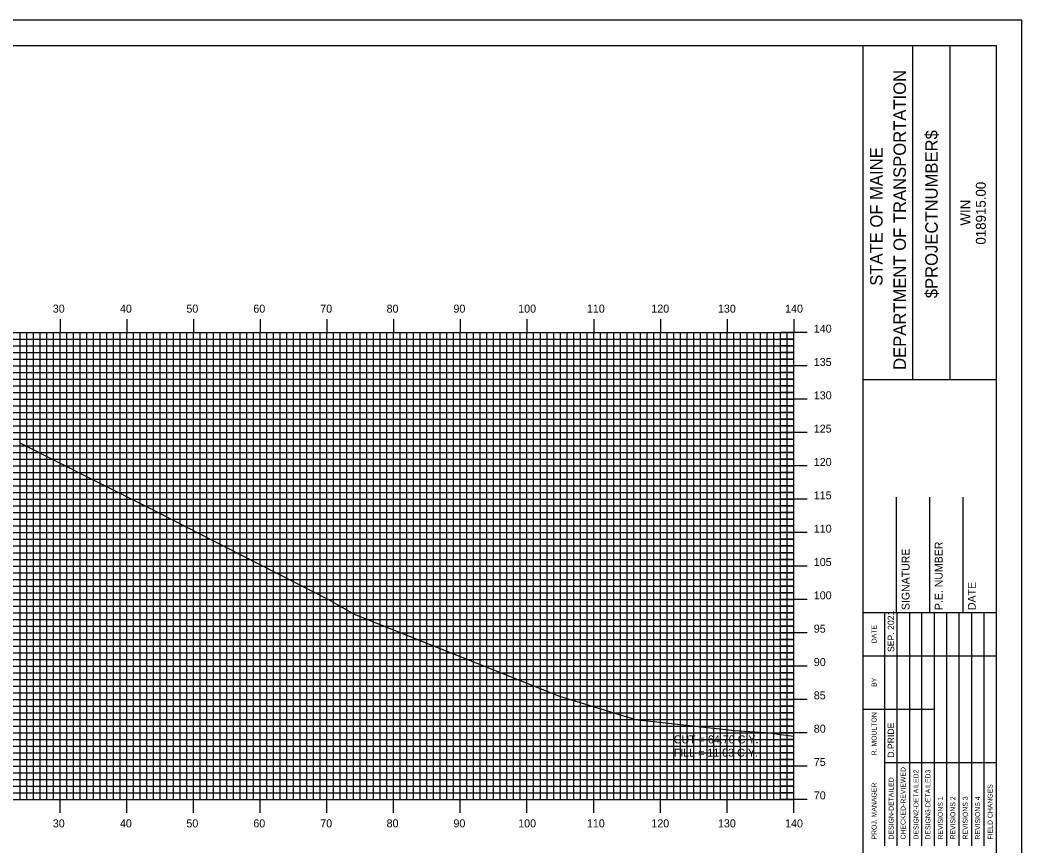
# Model space of a CAD drawing. Extents: x 859078 to 859421, y 364765 to 364985.
# Drawn here: x 859267.3 to 859417.6, y 364861.3 to 364985.2 of the extents above; entities that cross this region are included whole.
import ezdxf

# ---------------------------------------------------------------- set-up
doc = ezdxf.new("R2010")
doc.units = 0
for name, color, linetype in [('BORDER', 7, 'Continuous'), ('D_Text_Standard', 7, 'Continuous'), ('H_V ANNOTATION', 7, 'Continuous'), ('MAJOR', 7, 'Continuous'), ('MINOR', 7, 'Continuous'), ('PLOT BOUNDARY', 7, 'Continuous'), ('S_Roadway_Centerline', 7, 'Continuous')]:
    doc.layers.add(name, color=color, linetype=linetype)

msp = doc.modelspace()

# ---------------------------------------------------------------- linework, layer by layer
at = {"layer": 'BORDER'}
for p, q in [((859393.76, 364771.3), (859393.76, 364981.3)), ((859401.22, 364931.3), (859401.22, 364981.3)), ((859406.81, 364931.3), (859406.81, 364981.3)), ((859393.76, 364931.29), (859413.76, 364931.29)), ((859398.76, 364896.31), (859398.76, 364913.6)), ((859403.76, 364896.31), (859403.76, 364913.6)), ((859408.76, 364896.31), (859408.76, 364913.6)), ((859393.76, 364896.31), (859413.76, 364896.31))]:
    msp.add_line(p, q, dxfattribs=at)
msp.add_lwpolyline([(859093.76, 364771.3), (859413.76, 364771.3), (859413.76, 364981.3), (859093.76, 364981.3)], close=True, dxfattribs=at)
for points in [[(859396.99, 364889.81), (859396.99, 364896.31)], [(859398.85, 364861.31), (859398.85, 364896.31)], [(859400.72, 364896.31), (859400.72, 364861.31)], [(859402.58, 364861.31), (859402.58, 364896.31)], [(859404.45, 364861.31), (859404.45, 364896.31)], [(859406.31, 364861.31), (859406.31, 364896.31)], [(859408.17, 364861.31), (859408.17, 364896.31)], [(859410.04, 364861.31), (859410.04, 364896.31)], [(859411.9, 364861.31), (859411.9, 364896.31)], [(859396.99, 364861.31), (859396.99, 364894.9)], [(859393.76, 364889.81), (859413.76, 364889.81)], [(859393.76, 364881.81), (859396.99, 364881.81)], [(859396.99, 364881.81), (859404.44, 364881.81)], [(859396.99, 364873.81), (859413.76, 364873.81)]]:
    msp.add_lwpolyline(points, dxfattribs=at)
at = {"layer": 'MAJOR'}
for p, q in [((859273.36, 364940.31), (859273.36, 364938.3)), ((859283.36, 364940.31), (859283.36, 364938.3)), ((859293.36, 364940.31), (859293.36, 364938.3)), ((859303.36, 364940.31), (859303.36, 364938.3)), ((859313.36, 364940.31), (859313.36, 364938.3)), ((859323.36, 364940.31), (859323.36, 364938.3)), ((859333.36, 364940.31), (859333.36, 364938.3)), ((859343.36, 364940.31), (859343.36, 364938.3)), ((859353.36, 364940.31), (859353.36, 364938.3)), ((859363.36, 364940.31), (859363.36, 364938.3)), ((859373.36, 364940.31), (859373.36, 364938.3)), ((859383.36, 364940.31), (859383.36, 364938.3)), ((859103.36, 364938.3), (859383.36, 364938.3)), ((859103.36, 364938.3), (859383.36, 364938.3)), ((859273.36, 364868.3), (859273.36, 364938.3)), ((859283.36, 364868.3), (859283.36, 364938.3)), ((859293.36, 364868.3), (859293.36, 364938.3)), ((859303.36, 364868.3), (859303.36, 364938.3)), ((859313.36, 364868.3), (859313.36, 364938.3)), ((859323.36, 364868.3), (859323.36, 364938.3)), ((859333.36, 364868.3), (859333.36, 364938.3)), ((859343.36, 364868.3), (859343.36, 364938.3)), ((859353.36, 364868.3), (859353.36, 364938.3)), ((859363.36, 364868.3), (859363.36, 364938.3)), ((859373.36, 364868.3), (859373.36, 364938.3)), ((859385.36, 364938.3), (859381.36, 364938.3)), ((859383.36, 364868.3), (859383.36, 364938.3)), ((859383.36, 364868.3), (859383.36, 364938.3)), ((859103.36, 364933.3), (859383.36, 364933.3)), ((859385.36, 364933.3), (859381.36, 364933.3)), ((859103.36, 364928.3), (859383.36, 364928.3)), ((859385.36, 364928.3), (859381.36, 364928.3)), ((859103.36, 364923.3), (859383.36, 364923.3)), ((859385.36, 364923.3), (859381.36, 364923.3)), ((859103.36, 364918.3), (859383.36, 364918.3)), ((859385.36, 364918.3), (859381.36, 364918.3)), ((859103.36, 364913.3), (859383.36, 364913.3)), ((859385.36, 364913.3), (859381.36, 364913.3)), ((859103.36, 364908.3), (859383.36, 364908.3)), ((859385.36, 364908.3), (859381.36, 364908.3)), ((859103.36, 364903.3), (859383.36, 364903.3)), ((859385.36, 364903.3), (859381.36, 364903.3)), ((859103.36, 364898.3), (859383.36, 364898.3)), ((859385.36, 364898.3), (859381.36, 364898.3)), ((859103.36, 364893.3), (859383.36, 364893.3)), ((859385.36, 364893.3), (859381.36, 364893.3)), ((859103.36, 364888.3), (859383.36, 364888.3)), ((859385.36, 364888.3), (859381.36, 364888.3)), ((859103.36, 364883.3), (859383.36, 364883.3)), ((859385.36, 364883.3), (859381.36, 364883.3)), ((859103.36, 364878.3), (859383.36, 364878.3)), ((859385.36, 364878.3), (859381.36, 364878.3)), ((859103.36, 364873.3), (859383.36, 364873.3)), ((859385.36, 364873.3), (859381.36, 364873.3)), ((859103.36, 364868.3), (859383.36, 364868.3)), ((859103.36, 364868.3), (859383.36, 364868.3)), ((859273.36, 364866.3), (859273.36, 364868.3)), ((859283.36, 364866.3), (859283.36, 364868.3)), ((859293.36, 364866.3), (859293.36, 364868.3)), ((859303.36, 364866.3), (859303.36, 364868.3)), ((859313.36, 364866.3), (859313.36, 364868.3)), ((859323.36, 364866.3), (859323.36, 364868.3)), ((859333.36, 364866.3), (859333.36, 364868.3)), ((859343.36, 364866.3), (859343.36, 364868.3)), ((859353.36, 364866.3), (859353.36, 364868.3)), ((859363.36, 364866.3), (859363.36, 364868.3)), ((859373.36, 364866.3), (859373.36, 364868.3)), ((859385.36, 364868.3), (859381.36, 364868.3)), ((859383.36, 364866.3), (859383.36, 364868.3))]:
    msp.add_line(p, q, dxfattribs=at)
at = {"layer": 'MINOR'}
for p, q in [((859267.36, 364868.3), (859267.36, 364938.3)), ((859268.36, 364868.3), (859268.36, 364938.3)), ((859269.36, 364868.3), (859269.36, 364938.3)), ((859270.36, 364868.3), (859270.36, 364938.3)), ((859271.36, 364868.3), (859271.36, 364938.3)), ((859272.36, 364868.3), (859272.36, 364938.3)), ((859274.36, 364868.3), (859274.36, 364938.3)), ((859275.36, 364868.3), (859275.36, 364938.3)), ((859276.36, 364868.3), (859276.36, 364938.3)), ((859277.36, 364868.3), (859277.36, 364938.3)), ((859278.36, 364868.3), (859278.36, 364938.3)), ((859279.36, 364868.3), (859279.36, 364938.3)), ((859280.36, 364868.3), (859280.36, 364938.3)), ((859281.36, 364868.3), (859281.36, 364938.3)), ((859282.36, 364868.3), (859282.36, 364938.3)), ((859284.36, 364868.3), (859284.36, 364938.3)), ((859285.36, 364868.3), (859285.36, 364938.3)), ((859286.36, 364868.3), (859286.36, 364938.3)), ((859287.36, 364868.3), (859287.36, 364938.3)), ((859288.36, 364868.3), (859288.36, 364938.3)), ((859289.36, 364868.3), (859289.36, 364938.3)), ((859290.36, 364868.3), (859290.36, 364938.3)), ((859291.36, 364868.3), (859291.36, 364938.3)), ((859292.36, 364868.3), (859292.36, 364938.3)), ((859294.36, 364868.3), (859294.36, 364938.3)), ((859295.36, 364868.3), (859295.36, 364938.3)), ((859296.36, 364868.3), (859296.36, 364938.3)), ((859297.36, 364868.3), (859297.36, 364938.3)), ((859298.36, 364868.3), (859298.36, 364938.3)), ((859299.36, 364868.3), (859299.36, 364938.3)), ((859300.36, 364868.3), (859300.36, 364938.3)), ((859301.36, 364868.3), (859301.36, 364938.3)), ((859302.36, 364868.3), (859302.36, 364938.3)), ((859304.36, 364868.3), (859304.36, 364938.3)), ((859305.36, 364868.3), (859305.36, 364938.3)), ((859306.36, 364868.3), (859306.36, 364938.3)), ((859307.36, 364868.3), (859307.36, 364938.3)), ((859308.36, 364868.3), (859308.36, 364938.3)), ((859309.36, 364868.3), (859309.36, 364938.3)), ((859310.36, 364868.3), (859310.36, 364938.3)), ((859311.36, 364868.3), (859311.36, 364938.3)), ((859312.36, 364868.3), (859312.36, 364938.3)), ((859314.36, 364868.3), (859314.36, 364938.3)), ((859315.36, 364868.3), (859315.36, 364938.3)), ((859316.36, 364868.3), (859316.36, 364938.3)), ((859317.36, 364868.3), (859317.36, 364938.3)), ((859318.36, 364868.3), (859318.36, 364938.3)), ((859319.36, 364868.3), (859319.36, 364938.3)), ((859320.36, 364868.3), (859320.36, 364938.3)), ((859321.36, 364868.3), (859321.36, 364938.3)), ((859322.36, 364868.3), (859322.36, 364938.3)), ((859324.36, 364868.3), (859324.36, 364938.3)), ((859325.36, 364868.3), (859325.36, 364938.3)), ((859326.36, 364868.3), (859326.36, 364938.3)), ((859327.36, 364868.3), (859327.36, 364938.3)), ((859328.36, 364868.3), (859328.36, 364938.3)), ((859329.36, 364868.3), (859329.36, 364938.3)), ((859330.36, 364868.3), (859330.36, 364938.3)), ((859331.36, 364868.3), (859331.36, 364938.3)), ((859332.36, 364868.3), (859332.36, 364938.3)), ((859334.36, 364868.3), (859334.36, 364938.3)), ((859335.36, 364868.3), (859335.36, 364938.3)), ((859336.36, 364868.3), (859336.36, 364938.3)), ((859337.36, 364868.3), (859337.36, 364938.3)), ((859338.36, 364868.3), (859338.36, 364938.3)), ((859339.36, 364868.3), (859339.36, 364938.3)), ((859340.36, 364868.3), (859340.36, 364938.3)), ((859341.36, 364868.3), (859341.36, 364938.3)), ((859342.36, 364868.3), (859342.36, 364938.3)), ((859344.36, 364868.3), (859344.36, 364938.3)), ((859345.36, 364868.3), (859345.36, 364938.3)), ((859346.36, 364868.3), (859346.36, 364938.3)), ((859347.36, 364868.3), (859347.36, 364938.3)), ((859348.36, 364868.3), (859348.36, 364938.3)), ((859349.36, 364868.3), (859349.36, 364938.3)), ((859350.36, 364868.3), (859350.36, 364938.3)), ((859351.36, 364868.3), (859351.36, 364938.3)), ((859352.36, 364868.3), (859352.36, 364938.3)), ((859354.36, 364868.3), (859354.36, 364938.3)), ((859355.36, 364868.3), (859355.36, 364938.3)), ((859356.36, 364868.3), (859356.36, 364938.3)), ((859357.36, 364868.3), (859357.36, 364938.3)), ((859358.36, 364868.3), (859358.36, 364938.3)), ((859359.36, 364868.3), (859359.36, 364938.3)), ((859360.36, 364868.3), (859360.36, 364938.3)), ((859361.36, 364868.3), (859361.36, 364938.3)), ((859362.36, 364868.3), (859362.36, 364938.3)), ((859364.36, 364868.3), (859364.36, 364938.3)), ((859365.36, 364868.3), (859365.36, 364938.3)), ((859366.36, 364868.3), (859366.36, 364938.3)), ((859367.36, 364868.3), (859367.36, 364938.3)), ((859368.36, 364868.3), (859368.36, 364938.3)), ((859369.36, 364868.3), (859369.36, 364938.3)), ((859370.36, 364868.3), (859370.36, 364938.3)), ((859371.36, 364868.3), (859371.36, 364938.3)), ((859372.36, 364868.3), (859372.36, 364938.3)), ((859374.36, 364868.3), (859374.36, 364938.3)), ((859375.36, 364868.3), (859375.36, 364938.3)), ((859376.36, 364868.3), (859376.36, 364938.3)), ((859377.36, 364868.3), (859377.36, 364938.3)), ((859378.36, 364868.3), (859378.36, 364938.3)), ((859379.36, 364868.3), (859379.36, 364938.3)), ((859380.36, 364868.3), (859380.36, 364938.3)), ((859381.36, 364868.3), (859381.36, 364938.3)), ((859382.36, 364868.3), (859382.36, 364938.3)), ((859103.36, 364937.3), (859383.36, 364937.3)), ((859383.36, 364937.3), (859381.36, 364937.3)), ((859103.36, 364936.3), (859383.36, 364936.3)), ((859103.36, 364935.3), (859383.36, 364935.3)), ((859383.36, 364936.3), (859381.36, 364936.3)), ((859383.36, 364935.3), (859381.36, 364935.3)), ((859103.36, 364934.3), (859383.36, 364934.3)), ((859383.36, 364934.3), (859381.36, 364934.3)), ((859103.36, 364932.3), (859383.36, 364932.3)), ((859383.36, 364932.3), (859381.36, 364932.3)), ((859103.36, 364931.3), (859383.36, 364931.3)), ((859383.36, 364931.3), (859381.36, 364931.3)), ((859103.36, 364930.3), (859383.36, 364930.3)), ((859103.36, 364929.3), (859383.36, 364929.3)), ((859383.36, 364930.3), (859381.36, 364930.3)), ((859383.36, 364929.3), (859381.36, 364929.3)), ((859103.36, 364927.3), (859383.36, 364927.3)), ((859103.36, 364926.3), (859383.36, 364926.3)), ((859383.36, 364927.3), (859381.36, 364927.3)), ((859383.36, 364926.3), (859381.36, 364926.3)), ((859103.36, 364925.3), (859383.36, 364925.3)), ((859383.36, 364925.3), (859381.36, 364925.3)), ((859103.36, 364924.3), (859383.36, 364924.3)), ((859383.36, 364924.3), (859381.36, 364924.3)), ((859103.36, 364922.3), (859383.36, 364922.3)), ((859383.36, 364922.3), (859381.36, 364922.3)), ((859103.36, 364921.3), (859383.36, 364921.3)), ((859103.36, 364920.3), (859383.36, 364920.3)), ((859383.36, 364921.3), (859381.36, 364921.3)), ((859383.36, 364920.3), (859381.36, 364920.3)), ((859103.36, 364919.3), (859383.36, 364919.3)), ((859383.36, 364919.3), (859381.36, 364919.3)), ((859103.36, 364917.3), (859383.36, 364917.3)), ((859383.36, 364917.3), (859381.36, 364917.3)), ((859103.36, 364916.3), (859383.36, 364916.3)), ((859383.36, 364916.3), (859381.36, 364916.3)), ((859103.36, 364915.3), (859383.36, 364915.3)), ((859103.36, 364914.3), (859383.36, 364914.3)), ((859383.36, 364915.3), (859381.36, 364915.3)), ((859383.36, 364914.3), (859381.36, 364914.3)), ((859103.36, 364912.3), (859383.36, 364912.3)), ((859103.36, 364911.3), (859383.36, 364911.3)), ((859383.36, 364912.3), (859381.36, 364912.3)), ((859383.36, 364911.3), (859381.36, 364911.3)), ((859103.36, 364910.3), (859383.36, 364910.3)), ((859383.36, 364910.3), (859381.36, 364910.3)), ((859103.36, 364909.3), (859383.36, 364909.3)), ((859383.36, 364909.3), (859381.36, 364909.3)), ((859103.36, 364907.3), (859383.36, 364907.3)), ((859383.36, 364907.3), (859381.36, 364907.3)), ((859103.36, 364906.3), (859383.36, 364906.3)), ((859103.36, 364905.3), (859383.36, 364905.3)), ((859383.36, 364906.3), (859381.36, 364906.3)), ((859383.36, 364905.3), (859381.36, 364905.3)), ((859103.36, 364904.3), (859383.36, 364904.3)), ((859383.36, 364904.3), (859381.36, 364904.3)), ((859103.36, 364902.3), (859383.36, 364902.3)), ((859383.36, 364902.3), (859381.36, 364902.3)), ((859103.36, 364901.3), (859383.36, 364901.3)), ((859383.36, 364901.3), (859381.36, 364901.3)), ((859103.36, 364900.3), (859383.36, 364900.3)), ((859103.36, 364899.3), (859383.36, 364899.3)), ((859383.36, 364900.3), (859381.36, 364900.3)), ((859383.36, 364899.3), (859381.36, 364899.3)), ((859103.36, 364897.3), (859383.36, 364897.3)), ((859103.36, 364896.3), (859383.36, 364896.3)), ((859383.36, 364897.3), (859381.36, 364897.3)), ((859383.36, 364896.3), (859381.36, 364896.3)), ((859103.36, 364895.3), (859383.36, 364895.3)), ((859383.36, 364895.3), (859381.36, 364895.3)), ((859103.36, 364894.3), (859383.36, 364894.3)), ((859383.36, 364894.3), (859381.36, 364894.3)), ((859103.36, 364892.3), (859383.36, 364892.3)), ((859383.36, 364892.3), (859381.36, 364892.3)), ((859103.36, 364891.3), (859383.36, 364891.3)), ((859103.36, 364890.3), (859383.36, 364890.3)), ((859383.36, 364891.3), (859381.36, 364891.3)), ((859383.36, 364890.3), (859381.36, 364890.3)), ((859103.36, 364889.3), (859383.36, 364889.3)), ((859383.36, 364889.3), (859381.36, 364889.3)), ((859103.36, 364887.3), (859383.36, 364887.3)), ((859383.36, 364887.3), (859381.36, 364887.3)), ((859103.36, 364886.3), (859383.36, 364886.3)), ((859383.36, 364886.3), (859381.36, 364886.3)), ((859103.36, 364885.3), (859383.36, 364885.3)), ((859103.36, 364884.3), (859383.36, 364884.3)), ((859383.36, 364885.3), (859381.36, 364885.3)), ((859383.36, 364884.3), (859381.36, 364884.3)), ((859103.36, 364882.3), (859383.36, 364882.3)), ((859103.36, 364881.3), (859383.36, 364881.3)), ((859383.36, 364882.3), (859381.36, 364882.3)), ((859383.36, 364881.3), (859381.36, 364881.3)), ((859103.36, 364880.3), (859383.36, 364880.3)), ((859383.36, 364880.3), (859381.36, 364880.3)), ((859103.36, 364879.3), (859383.36, 364879.3)), ((859383.36, 364879.3), (859381.36, 364879.3)), ((859103.36, 364877.3), (859383.36, 364877.3)), ((859383.36, 364877.3), (859381.36, 364877.3)), ((859103.36, 364876.3), (859383.36, 364876.3)), ((859103.36, 364875.3), (859383.36, 364875.3)), ((859383.36, 364876.3), (859381.36, 364876.3)), ((859383.36, 364875.3), (859381.36, 364875.3)), ((859103.36, 364874.3), (859383.36, 364874.3)), ((859383.36, 364874.3), (859381.36, 364874.3)), ((859103.36, 364872.3), (859383.36, 364872.3)), ((859383.36, 364872.3), (859381.36, 364872.3)), ((859103.36, 364871.3), (859383.36, 364871.3)), ((859103.36, 364870.3), (859383.36, 364870.3)), ((859383.36, 364871.3), (859381.36, 364871.3)), ((859383.36, 364870.3), (859381.36, 364870.3)), ((859103.36, 364869.3), (859383.36, 364869.3)), ((859383.36, 364869.3), (859381.36, 364869.3))]:
    msp.add_line(p, q, dxfattribs=at)
at = {"layer": 'PLOT BOUNDARY'}
msp.add_lwpolyline([(859077.57, 364765.18), (859417.57, 364765.18), (859417.57, 364985.18), (859077.57, 364985.18)], close=True, dxfattribs=at)
at = {"layer": 'S_Roadway_Centerline'}
msp.add_lwpolyline([(859267.32, 364921.76), (859278.31, 364916.2), (859286.53, 364912.14), (859298.12, 364906.15), (859313.62, 364898.26), (859317.46, 364896.1), (859348.21, 364883.76), (859359.65, 364880.29), (859374.49, 364878.61), (859379.79, 364878.28), (859381.02, 364878.1), (859383.36, 364877.8)], dxfattribs=at)

# ---------------------------------------------------------------- texts
at = {"layer": 'BORDER'}
for s, height, p in [('DEPARTMENT OF TRANSPORTATION', 1.8635, (859400.17, 364932.71)), ('$PROJECTNUMBER$', 1.8635, (859404.94, 364943.46)), ('STATE OF MAINE', 1.8635, (859396.67, 364945.33)), ('018915.00', 1.491, (859412.15, 364951.5)), ('WIN', 1.491, (859409.83, 364954.36)), ('P.E. NUMBER', 1.1811, (859405.68, 364896.69)), ('SIGNATURE', 1.181, (859400.72, 364896.69)), ('DATE', 1.181, (859410.64, 364896.69)), ('SEP. 2021', 0.969, (859398.41, 364890.4)), ('DATE', 0.743, (859395.77, 364891.72)), ('BY', 0.743, (859395.77, 364885.18)), ('R. MOULTON', 0.745, (859395.77, 364874.91)), ('D.PRIDE', 0.969, (859398.41, 364874.55)), ('CHECKED-REVIEWED', 0.7455, (859400.12, 364862.28)), ('DESIGN2-DETAILED2', 0.7455, (859402.06, 364862.28)), ('DESIGN3-DETAILED3', 0.7455, (859403.85, 364862.28)), ('PROJ. MANAGER', 0.7455, (859395.77, 364862.28)), ('DESIGN-DETAILED', 0.7455, (859398.33, 364862.28)), ('FIELD CHANGES', 0.7455, (859413.17, 364862.28)), ('REVISIONS 1', 0.7455, (859405.71, 364862.28)), ('REVISIONS 2', 0.7455, (859407.58, 364862.28)), ('REVISIONS 3', 0.7455, (859409.44, 364862.28)), ('REVISIONS 4', 0.7455, (859411.3, 364862.28))]:
    msp.add_text(s, height=height, rotation=90, dxfattribs=at).set_placement(p)
at = {"layer": 'D_Text_Standard'}
for s, p in [('CUT = 64.70 C.Y.', (859365.36, 364876.7)), ('FILL = 11.03 C.Y.', (859365.36, 364874.71))]:
    msp.add_text(s, height=1.2, dxfattribs=at).set_placement(p)
at = {"layer": 'H_V ANNOTATION'}
for s, p in [('30', (859272.26, 364941.3)), ('40', (859282.33, 364941.3)), ('50', (859292.29, 364941.3)), ('60', (859302.33, 364941.3)), ('70', (859312.36, 364941.3)), ('80', (859322.31, 364941.3)), ('90', (859332.33, 364941.3)), ('100', (859342.04, 364941.3)), ('110', (859352.34, 364941.3)), ('120', (859362, 364941.3)), ('130', (859371.99, 364941.3)), ('140', (859382.06, 364941.3)), ('140', (859386.36, 364938.3)), ('135', (859386.36, 364933.3)), ('130', (859386.36, 364928.3)), ('125', (859386.36, 364923.3)), ('120', (859386.36, 364918.3)), ('115', (859386.36, 364913.3)), ('110', (859386.36, 364908.3)), ('105', (859386.36, 364903.3)), ('100', (859386.36, 364898.3)), ('95', (859386.36, 364893.3)), ('90', (859386.36, 364888.3)), ('85', (859386.36, 364883.3)), ('80', (859386.36, 364878.3)), ('75', (859386.36, 364873.3)), ('70', (859386.36, 364868.3)), ('30', (859272.26, 364864.1)), ('40', (859282.33, 364864.1)), ('50', (859292.29, 364864.1)), ('60', (859302.33, 364864.1)), ('70', (859312.36, 364864.1)), ('80', (859322.31, 364864.1)), ('90', (859332.33, 364864.1)), ('100', (859342.04, 364864.1)), ('110', (859352.34, 364864.1)), ('120', (859362, 364864.1)), ('130', (859371.99, 364864.1)), ('140', (859382.06, 364864.1))]:
    msp.add_text(s, height=1.2, dxfattribs=at).set_placement(p)

doc.saveas('drawing.dxf')
